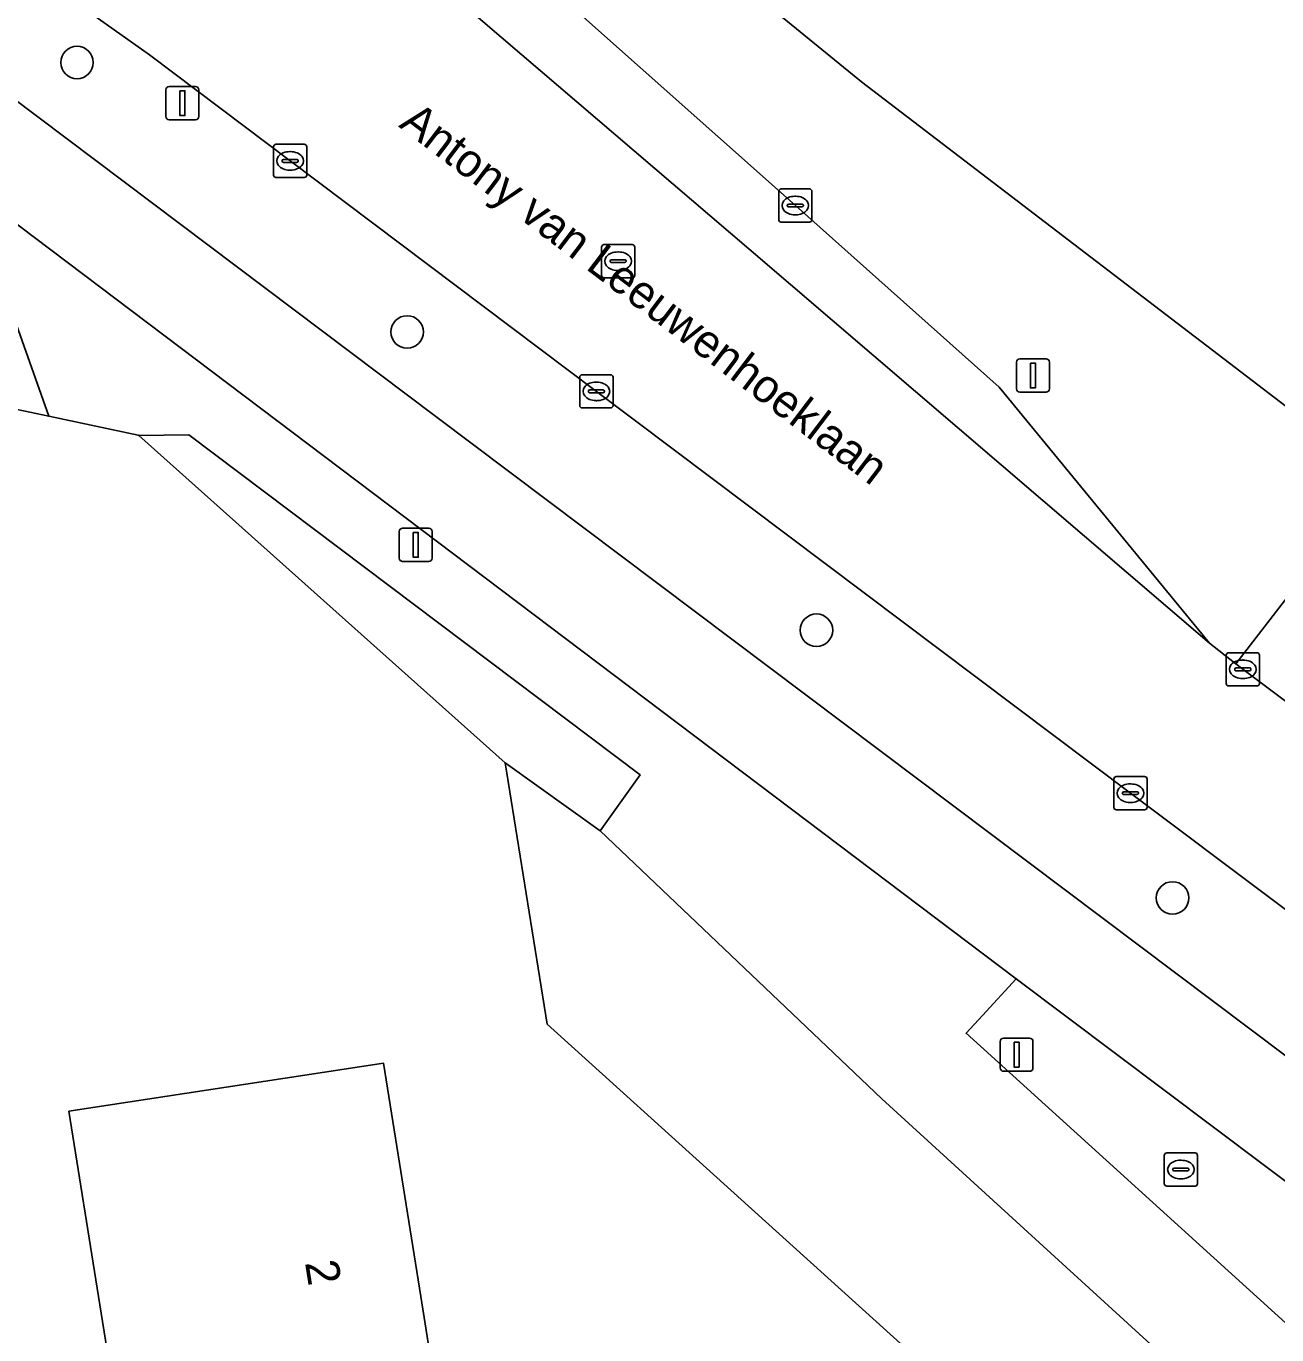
# Model space of a CAD drawing. Extents: x 159888 to 160761, y 384031 to 384750.
# Drawn here: x 160018.9 to 160056.55, y 384498.85 to 384538.25 of the extents above; entities that cross this region are included whole.
import ezdxf

# ---------------------------------------------------------------- set-up
doc = ezdxf.new("R2010")
doc.units = 0
for name, color, linetype in [('IMGEO_Berm_groen', 7, 'Continuous'), ('IMGEO_Boom', 7, 'Continuous'), ('IMGEO_Brandkraan', 7, 'Continuous'), ('IMGEO_Erf', 7, 'Continuous'), ('IMGEO_Fietspad_gesloten', 7, 'Continuous'), ('IMGEO_Groenvoorziening', 7, 'Continuous'), ('IMGEO_Hek', 7, 'Continuous'), ('IMGEO_Kolk', 7, 'Continuous'), ('IMGEO_Lichtmast', 7, 'Continuous'), ('IMGEO_Openbare_ruimte_label', 7, 'Continuous'), ('IMGEO_Pand', 7, 'Continuous'), ('IMGEO_Pand_nummerreeks', 7, 'Continuous'), ('IMGEO_Rijbaan_lokaal_open', 7, 'Continuous'), ('IMGEO_Rioolput', 7, 'Continuous'), ('IMGEO_Voetpad_open', 7, 'Continuous')]:
    doc.layers.add(name, color=color, linetype=linetype)

msp = doc.modelspace()

# ---------------------------------------------------------------- linework, layer by layer
at = {"layer": 'IMGEO_Berm_groen'}
msp.add_lwpolyline([(160052.141, 384515.156), (160036.065, 384527.255), (160033.506, 384529.181), (160026.846, 384534.194), (160022.615, 384537.386), (160020.244, 384539.075), (160018.872, 384540.033), (160018.323, 384539.157), (160017.098, 384537.235), (160017.533, 384536.804), (160031.234, 384526.495), (160105.836, 384470.365), (160106.003, 384470.24), (160106.621, 384471.076), (160108.141, 384473.131), (160101.659, 384477.982), (160099.829, 384479.351), (160085.029, 384490.505), (160069.4, 384502.204)], close=True, dxfattribs=at)
for points in [[(160048.701, 384509.565), (160047.684, 384508.463), (160047.191, 384507.929), (160057.459, 384498.614), (160058.403, 384497.799), (160061.763, 384494.626), (160061.875, 384494.502), (160062.22, 384494.123), (160062.609, 384493.502)], [(160063.384, 384492.443), (160065.699, 384490.622), (160101.231, 384464.252), (160103.177, 384466.847), (160104.02, 384467.971), (160048.701, 384509.565)]]:
    msp.add_lwpolyline(points, dxfattribs=at)
at = {"layer": 'IMGEO_Boom'}
for centre in [(160020.431, 384537.157), (160030.368, 384529.044), (160042.688, 384520.063), (160053.408, 384512.003)]:
    msp.add_circle(centre, 0.489, dxfattribs=at)
at = {"layer": 'IMGEO_Brandkraan'}
for p, q in [((160053.158, 384503.399), (160053.158, 384504.251)), ((160053.233, 384504.325), (160054.085, 384504.325)), ((160053.646, 384504.105), (160053.671, 384504.105)), ((160054.159, 384504.251), (160054.159, 384503.399)), ((160053.417, 384503.819), (160053.417, 384503.831)), ((160053.855, 384503.782), (160053.457, 384503.782)), ((160053.46, 384503.868), (160053.858, 384503.868)), ((160053.901, 384503.831), (160053.901, 384503.819)), ((160054.085, 384503.325), (160053.233, 384503.325)), ((160053.669, 384503.545), (160053.644, 384503.545))]:
    msp.add_line(p, q, dxfattribs=at)
for points in [[(160053.158, 384503.399), (160053.158, 384504.251)], [(160053.233, 384504.325), (160054.085, 384504.325)], [(160054.159, 384504.251), (160054.159, 384503.399)], [(160054.085, 384503.325), (160053.233, 384503.325)]]:
    msp.add_lwpolyline(points, dxfattribs=at)
for centre, radius, start, end in [((160053.235, 384504.249), 0.0765, 91.552, 178.448), ((160053.235, 384504.249), 0.0765, 91.552, 178.448), ((160054.083, 384504.249), 0.0765, 1.552, 88.448), ((160054.083, 384504.249), 0.0765, 1.552, 88.448), ((160053.457, 384503.828), 0.0403, 85.8775, 175.7526), ((160053.454, 384503.818), 0.0366, 178.938, 274.7102), ((160053.858, 384503.825), 0.043, 264.8664, 352.4533), ((160053.862, 384503.83), 0.0386, 1.7309, 96.639), ((160053.235, 384503.401), 0.0765, 181.552, 268.448), ((160053.235, 384503.401), 0.0765, 181.552, 268.448), ((160054.083, 384503.401), 0.0765, 271.552, 358.448), ((160054.083, 384503.401), 0.0765, 271.552, 358.448)]:
    msp.add_arc(centre, radius, start, end, dxfattribs=at)
for centre, major_axis, ratio, start_param, end_param in [((160053.645, 384503.825), (-0.387, 0.002), 0.722429, 4.712389, 7.853982), ((160053.67, 384503.825), (-0.39, 0.002), 0.717154, 1.570796, 4.712389)]:
    msp.add_ellipse(centre, major_axis=major_axis, ratio=ratio, start_param=start_param, end_param=end_param, dxfattribs=at)
at = {"layer": 'IMGEO_Erf'}
for points in [[(160057.163, 384547.816), (160058.271, 384548.509), (160058.141, 384548.718), (160058.407, 384548.883), (160056.714, 384551.521), (160057.369, 384550.381), (160040.209, 384539.742), (160039.539, 384540.809), (160039.158, 384540.572), (160044.048, 384536.578), (160058.403, 384525.598), (160074.056, 384513.832), (160092.698, 384500.015), (160112.975, 384485.03), (160116.883, 384487.168), (160131.986, 384495.431), (160131.163, 384496.735), (160116.313, 384487.517), (160116.183, 384487.726), (160114.737, 384486.834), (160114.554, 384487.129), (160113.873, 384486.708), (160109.069, 384494.434), (160106.102, 384494.625)], [(160010.303, 384467.633), (160048.801, 384470.599), (160056.378, 384488.496), (160034.585, 384508.205), (160033.315, 384516.066), (160022.294, 384525.925), (160022.276, 384525.941), (160019.582, 384526.507), (160013.286, 384527.83)]]:
    msp.add_lwpolyline(points, dxfattribs=at)
msp.add_lwpolyline([(160022.029, 384494.05), (160021.08, 384500), (160020.189, 384505.581), (160029.654, 384507.03), (160030.777, 384500), (160031.494, 384495.507)], close=True, dxfattribs=at)
at = {"layer": 'IMGEO_Fietspad_gesloten'}
for points in [[(160023.334, 384547.687), (160025.208, 384545.454), (160028.647, 384541.821), (160040.653, 384531.549), (160054.515, 384519.676), (160048.192, 384527.378), (160042.053, 384532.85), (160032.705, 384541.175)], [(160176.501, 384417.329), (160108.604, 384468.298), (160108.46, 384468.406), (160106.003, 384470.24), (160105.836, 384470.365), (160031.234, 384526.495), (160017.533, 384536.804), (160015.798, 384534.417), (160017.707, 384532.975), (160048.701, 384509.565), (160104.02, 384467.971), (160106.735, 384465.918), (160131.786, 384447.047), (160174.693, 384414.967)]]:
    msp.add_lwpolyline(points, dxfattribs=at)
at = {"layer": 'IMGEO_Groenvoorziening'}
for points in [[(160023.801, 384525.949), (160022.294, 384525.925), (160033.315, 384516.066), (160036.177, 384514.025), (160037.38, 384515.709)], [(160036.177, 384514.025), (160033.315, 384516.066), (160034.585, 384508.205), (160056.378, 384488.496), (160058.462, 384493.417), (160056.29, 384495.399), (160053.556, 384497.825), (160044.659, 384505.955)]]:
    msp.add_lwpolyline(points, close=True, dxfattribs=at)
msp.add_lwpolyline([(160063.2, 384518.984), (160063.554, 384519.484), (160058.511, 384523.2), (160055.316, 384519.049), (160055.524, 384518.887), (160069.487, 384508.403)], dxfattribs=at)
at = {"layer": 'IMGEO_Hek'}
msp.add_lwpolyline([(160022.276, 384525.941), (160022.294, 384525.925), (160033.315, 384516.066), (160034.585, 384508.205), (160056.378, 384488.496)], dxfattribs=at)
at = {"layer": 'IMGEO_Kolk'}
for p, q in [((160026.345, 384533.768), (160026.345, 384534.62)), ((160026.42, 384534.694), (160027.272, 384534.694)), ((160026.833, 384534.474), (160026.858, 384534.474)), ((160027.346, 384534.62), (160027.346, 384533.768)), ((160026.604, 384534.188), (160026.604, 384534.2)), ((160027.042, 384534.151), (160026.644, 384534.151)), ((160026.647, 384534.237), (160027.045, 384534.237)), ((160027.088, 384534.2), (160027.088, 384534.188)), ((160027.272, 384533.694), (160026.42, 384533.694)), ((160026.856, 384533.914), (160026.831, 384533.914)), ((160041.552, 384532.424), (160041.552, 384533.276)), ((160041.627, 384533.35), (160042.479, 384533.35)), ((160042.553, 384533.276), (160042.553, 384532.424)), ((160041.811, 384532.844), (160041.811, 384532.856)), ((160042.249, 384532.807), (160041.851, 384532.807)), ((160041.854, 384532.893), (160042.252, 384532.893)), ((160042.04, 384533.13), (160042.065, 384533.13)), ((160042.295, 384532.856), (160042.295, 384532.844)), ((160042.063, 384532.57), (160042.038, 384532.57)), ((160042.479, 384532.35), (160041.627, 384532.35)), ((160035.564, 384526.829), (160035.564, 384527.681)), ((160035.639, 384527.755), (160036.491, 384527.755)), ((160036.565, 384527.681), (160036.565, 384526.829)), ((160035.823, 384527.249), (160035.823, 384527.261)), ((160035.866, 384527.298), (160036.264, 384527.298)), ((160036.052, 384527.535), (160036.077, 384527.535)), ((160036.307, 384527.261), (160036.307, 384527.249)), ((160036.261, 384527.212), (160035.863, 384527.212)), ((160036.075, 384526.975), (160036.05, 384526.975)), ((160036.491, 384526.755), (160035.639, 384526.755)), ((160055.098, 384519.387), (160055.95, 384519.387)), ((160055.023, 384518.461), (160055.023, 384519.313)), ((160055.511, 384519.167), (160055.536, 384519.167)), ((160056.024, 384519.313), (160056.024, 384518.461)), ((160055.282, 384518.881), (160055.282, 384518.893)), ((160055.72, 384518.844), (160055.322, 384518.844)), ((160055.325, 384518.93), (160055.723, 384518.93)), ((160055.534, 384518.607), (160055.509, 384518.607)), ((160055.766, 384518.893), (160055.766, 384518.881)), ((160055.95, 384518.387), (160055.098, 384518.387)), ((160051.64, 384514.73), (160051.64, 384515.582)), ((160051.715, 384515.656), (160052.567, 384515.656)), ((160052.128, 384515.436), (160052.153, 384515.436)), ((160052.641, 384515.582), (160052.641, 384514.73)), ((160051.899, 384515.15), (160051.899, 384515.162)), ((160052.337, 384515.113), (160051.939, 384515.113)), ((160051.942, 384515.199), (160052.34, 384515.199)), ((160052.383, 384515.162), (160052.383, 384515.15)), ((160052.567, 384514.656), (160051.715, 384514.656)), ((160052.151, 384514.876), (160052.126, 384514.876))]:
    msp.add_line(p, q, dxfattribs=at)
for points in [[(160026.345, 384533.768), (160026.345, 384534.62)], [(160026.42, 384534.694), (160027.272, 384534.694)], [(160027.346, 384534.62), (160027.346, 384533.768)], [(160027.272, 384533.694), (160026.42, 384533.694)], [(160041.552, 384532.424), (160041.552, 384533.276)], [(160041.627, 384533.35), (160042.479, 384533.35)], [(160042.553, 384533.276), (160042.553, 384532.424)], [(160042.479, 384532.35), (160041.627, 384532.35)], [(160035.564, 384526.829), (160035.564, 384527.681)], [(160035.639, 384527.755), (160036.491, 384527.755)], [(160036.565, 384527.681), (160036.565, 384526.829)], [(160036.491, 384526.755), (160035.639, 384526.755)], [(160055.098, 384519.387), (160055.95, 384519.387)], [(160055.023, 384518.461), (160055.023, 384519.313)], [(160056.024, 384519.313), (160056.024, 384518.461)], [(160055.95, 384518.387), (160055.098, 384518.387)], [(160051.64, 384514.73), (160051.64, 384515.582)], [(160051.715, 384515.656), (160052.567, 384515.656)], [(160052.641, 384515.582), (160052.641, 384514.73)], [(160052.567, 384514.656), (160051.715, 384514.656)]]:
    msp.add_lwpolyline(points, dxfattribs=at)
for centre, radius, start, end in [((160026.422, 384534.618), 0.0765, 91.552, 178.448), ((160026.422, 384534.618), 0.0765, 91.552, 178.448), ((160027.27, 384534.618), 0.0765, 1.552, 88.448), ((160027.27, 384534.618), 0.0765, 1.552, 88.448), ((160026.644, 384534.197), 0.0403, 85.8775, 175.7526), ((160026.641, 384534.187), 0.0366, 178.938, 274.7102), ((160027.045, 384534.194), 0.043, 264.8664, 352.4533), ((160027.049, 384534.199), 0.0386, 1.7309, 96.639), ((160026.422, 384533.77), 0.0765, 181.552, 268.448), ((160026.422, 384533.77), 0.0765, 181.552, 268.448), ((160027.27, 384533.77), 0.0765, 271.552, 358.448), ((160027.27, 384533.77), 0.0765, 271.552, 358.448), ((160041.629, 384533.274), 0.0765, 91.552, 178.448), ((160041.629, 384533.274), 0.0765, 91.552, 178.448), ((160042.477, 384533.274), 0.0765, 1.552, 88.448), ((160042.477, 384533.274), 0.0765, 1.552, 88.448), ((160041.851, 384532.853), 0.0403, 85.8775, 175.7526), ((160041.848, 384532.843), 0.0366, 178.938, 274.7102), ((160042.252, 384532.85), 0.043, 264.8664, 352.4533), ((160042.256, 384532.855), 0.0386, 1.7309, 96.639), ((160041.629, 384532.426), 0.0765, 181.552, 268.448), ((160041.629, 384532.426), 0.0765, 181.552, 268.448), ((160042.477, 384532.426), 0.0765, 271.552, 358.448), ((160042.477, 384532.426), 0.0765, 271.552, 358.448), ((160035.641, 384527.679), 0.0765, 91.552, 178.448), ((160035.641, 384527.679), 0.0765, 91.552, 178.448), ((160036.489, 384527.679), 0.0765, 1.552, 88.448), ((160036.489, 384527.679), 0.0765, 1.552, 88.448), ((160035.863, 384527.258), 0.0403, 85.8775, 175.7526), ((160035.86, 384527.248), 0.0366, 178.938, 274.7102), ((160036.264, 384527.255), 0.043, 264.8664, 352.4533), ((160036.268, 384527.26), 0.0386, 1.7309, 96.639), ((160035.641, 384526.831), 0.0765, 181.552, 268.448), ((160035.641, 384526.831), 0.0765, 181.552, 268.448), ((160036.489, 384526.831), 0.0765, 271.552, 358.448), ((160036.489, 384526.831), 0.0765, 271.552, 358.448), ((160055.1, 384519.311), 0.0765, 91.552, 178.448), ((160055.1, 384519.311), 0.0765, 91.552, 178.448), ((160055.948, 384519.311), 0.0765, 1.552, 88.448), ((160055.948, 384519.311), 0.0765, 1.552, 88.448), ((160055.322, 384518.89), 0.0403, 85.8775, 175.7526), ((160055.319, 384518.88), 0.0366, 178.938, 274.7102), ((160055.723, 384518.887), 0.043, 264.8664, 352.4533), ((160055.727, 384518.892), 0.0386, 1.7309, 96.639), ((160055.1, 384518.463), 0.0765, 181.552, 268.448), ((160055.1, 384518.463), 0.0765, 181.552, 268.448), ((160055.948, 384518.463), 0.0765, 271.552, 358.448), ((160055.948, 384518.463), 0.0765, 271.552, 358.448), ((160051.717, 384515.58), 0.0765, 91.552, 178.448), ((160051.717, 384515.58), 0.0765, 91.552, 178.448), ((160052.565, 384515.58), 0.0765, 1.552, 88.448), ((160052.565, 384515.58), 0.0765, 1.552, 88.448), ((160051.939, 384515.159), 0.0403, 85.8775, 175.7526), ((160051.936, 384515.149), 0.0366, 178.938, 274.7102), ((160052.34, 384515.156), 0.043, 264.8664, 352.4533), ((160052.344, 384515.161), 0.0386, 1.7309, 96.639), ((160051.717, 384514.732), 0.0765, 181.552, 268.448), ((160051.717, 384514.732), 0.0765, 181.552, 268.448), ((160052.565, 384514.732), 0.0765, 271.552, 358.448), ((160052.565, 384514.732), 0.0765, 271.552, 358.448)]:
    msp.add_arc(centre, radius, start, end, dxfattribs=at)
for centre, major_axis, ratio, start_param, end_param in [((160026.832, 384534.194), (-0.387, 0.002), 0.722429, 4.712389, 7.853982), ((160026.857, 384534.194), (-0.39, 0.002), 0.717154, 1.570796, 4.712389), ((160042.039, 384532.85), (-0.387, 0.002), 0.722429, 4.712389, 7.853982), ((160042.064, 384532.85), (-0.39, 0.002), 0.717154, 1.570796, 4.712389), ((160036.051, 384527.255), (-0.387, 0.002), 0.722429, 4.712389, 7.853982), ((160036.076, 384527.255), (-0.39, 0.002), 0.717154, 1.570796, 4.712389), ((160055.51, 384518.887), (-0.387, 0.002), 0.722429, 4.712389, 7.853982), ((160055.535, 384518.887), (-0.39, 0.002), 0.717154, 1.570796, 4.712389), ((160052.127, 384515.156), (-0.387, 0.002), 0.722429, 4.712389, 7.853982), ((160052.152, 384515.156), (-0.39, 0.002), 0.717154, 1.570796, 4.712389)]:
    msp.add_ellipse(centre, major_axis=major_axis, ratio=ratio, start_param=start_param, end_param=end_param, dxfattribs=at)
at = {"layer": 'IMGEO_Lichtmast'}
for p, q in [((160023.108, 384535.533), (160023.108, 384536.333)), ((160023.108, 384536.333), (160023.108, 384535.533)), ((160023.208, 384536.433), (160023.998, 384536.433)), ((160023.998, 384536.433), (160023.208, 384536.433)), ((160024.098, 384536.333), (160024.098, 384535.533)), ((160024.098, 384535.533), (160024.098, 384536.333)), ((160023.998, 384535.433), (160023.208, 384535.433)), ((160023.208, 384535.433), (160023.998, 384535.433)), ((160048.709, 384527.333), (160048.709, 384528.133)), ((160048.709, 384528.133), (160048.709, 384527.333)), ((160048.809, 384528.233), (160049.599, 384528.233)), ((160049.599, 384528.233), (160048.809, 384528.233)), ((160049.699, 384528.133), (160049.699, 384527.333)), ((160049.699, 384527.333), (160049.699, 384528.133)), ((160049.599, 384527.233), (160048.809, 384527.233)), ((160048.809, 384527.233), (160049.599, 384527.233)), ((160030.132, 384522.234), (160030.132, 384523.034)), ((160030.132, 384523.034), (160030.132, 384522.234)), ((160030.232, 384523.134), (160031.022, 384523.134)), ((160031.022, 384523.134), (160030.232, 384523.134)), ((160031.122, 384523.034), (160031.122, 384522.234)), ((160031.122, 384522.234), (160031.122, 384523.034)), ((160031.022, 384522.134), (160030.232, 384522.134)), ((160030.232, 384522.134), (160031.022, 384522.134)), ((160048.216, 384506.883), (160048.216, 384507.683)), ((160048.216, 384507.683), (160048.216, 384506.883)), ((160048.316, 384507.783), (160049.106, 384507.783)), ((160049.106, 384507.783), (160048.316, 384507.783)), ((160049.206, 384507.683), (160049.206, 384506.883)), ((160049.206, 384506.883), (160049.206, 384507.683)), ((160049.106, 384506.783), (160048.316, 384506.783)), ((160048.316, 384506.783), (160049.106, 384506.783))]:
    msp.add_line(p, q, dxfattribs=at)
for points in [[(160023.528, 384536.308), (160023.678, 384536.308), (160023.678, 384535.558), (160023.528, 384535.558), (160023.528, 384536.308)], [(160049.129, 384528.108), (160049.279, 384528.108), (160049.279, 384527.358), (160049.129, 384527.358), (160049.129, 384528.108)], [(160030.552, 384523.009), (160030.702, 384523.009), (160030.702, 384522.259), (160030.552, 384522.259), (160030.552, 384523.009)], [(160048.636, 384507.658), (160048.786, 384507.658), (160048.786, 384506.908), (160048.636, 384506.908), (160048.636, 384507.658)]]:
    msp.add_lwpolyline(points, dxfattribs=at)
for centre, start, end in [((160023.208, 384536.333), 90, 180), ((160023.208, 384536.333), 90, 180), ((160023.998, 384536.333), 0, 90), ((160023.998, 384536.333), 360, 90), ((160023.208, 384535.533), 180, 270), ((160023.208, 384535.533), 180, 270), ((160023.998, 384535.533), 270, 0), ((160023.998, 384535.533), 270, 0), ((160048.809, 384528.133), 90, 180), ((160048.809, 384528.133), 90, 180), ((160049.599, 384528.133), 0, 90), ((160049.599, 384528.133), 360, 90), ((160048.809, 384527.333), 180, 270), ((160048.809, 384527.333), 180, 270), ((160049.599, 384527.333), 270, 0), ((160049.599, 384527.333), 270, 0), ((160030.232, 384523.034), 90, 180), ((160030.232, 384523.034), 90, 180), ((160031.022, 384523.034), 0, 90), ((160031.022, 384523.034), 360, 90), ((160030.232, 384522.234), 180, 270), ((160030.232, 384522.234), 180, 270), ((160031.022, 384522.234), 270, 0), ((160031.022, 384522.234), 270, 0), ((160048.316, 384507.683), 90, 180), ((160048.316, 384507.683), 90, 180), ((160049.106, 384507.683), 0, 90), ((160049.106, 384507.683), 360, 90), ((160048.316, 384506.883), 180, 270), ((160048.316, 384506.883), 180, 270), ((160049.106, 384506.883), 270, 0), ((160049.106, 384506.883), 270, 0)]:
    msp.add_arc(centre, 0.1, start, end, dxfattribs=at)
at = {"layer": 'IMGEO_Pand'}
msp.add_lwpolyline([(160022.029, 384494.05), (160031.494, 384495.507), (160030.777, 384500), (160029.654, 384507.03), (160020.189, 384505.581), (160021.08, 384500)], close=True, dxfattribs=at)
at = {"layer": 'IMGEO_Rijbaan_lokaal_open'}
for points in [[(160004.593, 384555.792), (160003.671, 384556.554), (160000.008, 384552.961), (160002.133, 384551.2), (160006.47, 384547.854), (160006.572, 384547.79), (160018.872, 384540.033), (160020.244, 384539.075), (160022.615, 384537.386), (160026.846, 384534.194), (160033.506, 384529.181), (160036.065, 384527.255), (160052.141, 384515.156), (160069.4, 384502.204), (160085.029, 384490.505), (160099.829, 384479.351), (160101.659, 384477.982), (160104.655, 384481.987), (160081.935, 384499.068), (160079.45, 384500.937), (160069.487, 384508.403), (160055.524, 384518.887)], [(160055.524, 384518.887), (160055.316, 384519.049), (160055.271, 384519.085), (160054.515, 384519.676), (160040.653, 384531.549), (160028.647, 384541.821), (160022.586, 384547.03), (160022.531, 384547.078), (160021.295, 384548.073), (160018.255, 384550.575)]]:
    msp.add_lwpolyline(points, dxfattribs=at)
at = {"layer": 'IMGEO_Rioolput'}
for p, q in [((160036.218, 384530.748), (160036.218, 384531.6)), ((160036.293, 384531.674), (160037.145, 384531.674)), ((160037.219, 384531.6), (160037.219, 384530.748)), ((160036.477, 384531.168), (160036.477, 384531.18)), ((160036.52, 384531.217), (160036.918, 384531.217)), ((160036.706, 384531.454), (160036.731, 384531.454)), ((160036.961, 384531.18), (160036.961, 384531.168)), ((160036.915, 384531.131), (160036.517, 384531.131)), ((160036.729, 384530.894), (160036.704, 384530.894)), ((160037.145, 384530.674), (160036.293, 384530.674))]:
    msp.add_line(p, q, dxfattribs=at)
for points in [[(160036.218, 384530.748), (160036.218, 384531.6)], [(160036.293, 384531.674), (160037.145, 384531.674)], [(160037.219, 384531.6), (160037.219, 384530.748)], [(160037.145, 384530.674), (160036.293, 384530.674)]]:
    msp.add_lwpolyline(points, dxfattribs=at)
for centre, radius, start, end in [((160036.295, 384531.598), 0.0765, 91.552, 178.448), ((160036.295, 384531.598), 0.0765, 91.552, 178.448), ((160037.143, 384531.598), 0.0765, 1.552, 88.448), ((160037.143, 384531.598), 0.0765, 1.552, 88.448), ((160036.517, 384531.177), 0.0403, 85.8775, 175.7526), ((160036.922, 384531.179), 0.0386, 1.7309, 96.639), ((160036.514, 384531.167), 0.0366, 178.938, 274.7102), ((160036.918, 384531.174), 0.043, 264.8664, 352.4533), ((160036.295, 384530.75), 0.0765, 181.552, 268.448), ((160036.295, 384530.75), 0.0765, 181.552, 268.448), ((160037.143, 384530.75), 0.0765, 271.552, 358.448), ((160037.143, 384530.75), 0.0765, 271.552, 358.448)]:
    msp.add_arc(centre, radius, start, end, dxfattribs=at)
for centre, major_axis, ratio, start_param, end_param in [((160036.705, 384531.174), (-0.387, 0.002), 0.722429, 4.712389, 7.853982), ((160036.73, 384531.174), (-0.39, 0.002), 0.717154, 1.570796, 4.712389)]:
    msp.add_ellipse(centre, major_axis=major_axis, ratio=ratio, start_param=start_param, end_param=end_param, dxfattribs=at)
at = {"layer": 'IMGEO_Voetpad_open'}
for points in [[(160058.403, 384525.598), (160044.048, 384536.578), (160039.158, 384540.572), (160036.783, 384539.121), (160032.781, 384545.559), (160030.139, 384547.584), (160028.731, 384549.365), (160021.797, 384560.469)], [(160024.426, 384550.63), (160025.015, 384549.778), (160027.848, 384545.939), (160029.847, 384543.688), (160032.705, 384541.175), (160042.053, 384532.85), (160048.192, 384527.378), (160054.515, 384519.676), (160055.271, 384519.085), (160055.316, 384519.049), (160058.511, 384523.2), (160063.554, 384519.484), (160063.2, 384518.984), (160082.505, 384504.558), (160081.229, 384502.849), (160073.541, 384508.626), (160073.152, 384508.109)], [(160010.671, 384536.314), (160013.286, 384527.83), (160019.582, 384526.507), (160017.336, 384532.83)]]:
    msp.add_lwpolyline(points, dxfattribs=at)
msp.add_lwpolyline([(160017.707, 384532.975), (160017.336, 384532.83), (160019.582, 384526.507), (160022.276, 384525.941), (160022.294, 384525.925), (160023.801, 384525.949), (160037.38, 384515.709), (160036.177, 384514.025), (160044.659, 384505.955), (160053.556, 384497.825), (160056.29, 384495.399), (160058.403, 384497.799), (160057.459, 384498.614), (160047.191, 384507.929), (160047.684, 384508.463), (160048.701, 384509.565)], close=True, dxfattribs=at)

# ---------------------------------------------------------------- texts
at = {"layer": 'IMGEO_Openbare_ruimte_label'}
msp.add_text('Antony van Leeuwenhoeklaan', height=1, rotation=322.7633, dxfattribs=at).set_placement((160030.088, 384535.236))
at = {"layer": 'IMGEO_Pand_nummerreeks'}
msp.add_text('2', height=1, rotation=279.0697, dxfattribs=at).set_placement((160027.291, 384501.024))

doc.saveas('drawing.dxf')
